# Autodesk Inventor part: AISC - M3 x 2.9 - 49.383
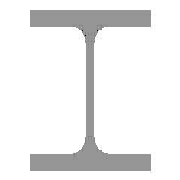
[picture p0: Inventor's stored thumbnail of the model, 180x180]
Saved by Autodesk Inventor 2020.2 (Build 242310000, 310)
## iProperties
_CCFamilyMember: 14
_CCFamilyDisplayName: ANSI M - M-Shape — Sizes in parentheses have been withdrawn
_FrameMemberDoc: Frame Member File
_Version: 15.0.0
_GetPNFromCC: 1
Created: 2020-01
Part Number: AISC - M3 x 2.9 - 49.383
Material: Steel, Mild
Description: M-Shape
Document SubType Name: Modeling
Standard: ANSI
Designer: thira
Standards Organization: ANSI
Language: en-US
Size Designation: M3 x 2.9
Categories: <MemberInstance><Categories><Category DisplayName="Structural Shapes" InternalName="089c4875-fa83-4c05-b084-43b9cc11f5ed" Mnemonic="GRDR"><CategoryParameter Dis
Stock Number: M3 x 2.9
Density: 7.85 g/cm^3
Appearance: Semi-Polished
G_L: 49.383 in
G_W: 2.250 in
G_H: 3.000 in
+2923C170-05DA-4238-8417-804BEE138335+CUTDETAIL1: Miter 45.00 deg
+5A0D731E-022E-4378-A517-99784A717457+CUTDETAIL2: Miter 45.00 deg
IsCustomPart: 1
Author: thira
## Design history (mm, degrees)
node "Start Plane"
node "End Plane"
sketch "Sketch"
  geometry: L1 (-28.575, -38.1)-(-28.575, -34.798); L2 (-28.575, -34.798)-(-10.541, -34.798); L3 (-1.143, -25.4)-(-1.143, 0); L4 (-1.143, 0)-(0, 0); L5 (0, 0)-(0, -38.1); L6 (0, -38.1)-(-28.575, -38.1); L7 (-60, 0)-(80, 0); L8 (0, -60)-(0, 80); L9 (28.575, -38.1)-(28.575, -34.798); L10 (28.575, -34.798)-(10.541, -34.798); L11 (0, -38.1)-(28.575, -38.1); L12 (1.143, -25.4)-(1.143, 0); L13 (1.143, 0)-(0, 0); L14 (-28.575, 38.1)-(-28.575, 34.798); L15 (0, 38.1)-(-28.575, 38.1); L16 (0, 38.1)-(28.575, 38.1); L17 (28.575, 34.798)-(10.541, 34.798); L18 (-28.575, 34.798)-(-10.541, 34.798); L19 (1.143, 25.4)-(1.143, 0); L20 (-1.143, 25.4)-(-1.143, 0); L21 (28.575, 38.1)-(28.575, 34.798); L22 (0, 108)-(0, -88) reference; L23 (-88, 0)-(108, 0) reference; A1 r 9.398 centre (-10.541, 25.4) between (-1.143, 25.4) and (-10.541, 34.798); A2 r 9.398 centre (10.541, 25.4) between (10.541, 34.798) and (1.143, 25.4); A3 r 9.398 centre (10.541, -25.4) between (1.143, -25.4) and (10.541, -34.798); A4 r 9.398 centre (-10.541, -25.4) between (-10.541, -34.798) and (-1.143, -25.4); 4 further points
  constraints: 42 end point, 11 symmetric about line, 8 point on circle, 8 point on line, 8 tangent, 4 centre point, 4 collinear, 4 parallel, 3 equal radius, 1 perpendicular, 1 vertical, 13 other
  dimensions: "d1" = 38.1 vertical distance of L1.start L3.end (= 0.5 x G_H); "d2" = 3.302 distance between parallel lines of L2 L6 (= G_T1); "d3" = 28.575 distance from line of L5.end L1 (= 0.5 x G_W); "d4" = 1.143 distance between parallel lines of L5 L3 (= 0.5 x G_T); "d13" = 9.398 radius of A1 (= G_IR)
extrude "Body" new body sketch "Sketch" stored distance "d5" = 1254.32157 (= G_L); taper "d6" = 0 deg
node "Driven Length"
  sketch "Sketch4"
    geometry: L1 (0, 0)-(10, 0) reference
    constraints: 2 end point, 1 horizontal
  workplane "Work Plane3"
  sketch "Sketch5"
    geometry: L1 (-2, -27.161)-(12, -27.161) reference; L2 (-2, 1227.161)-(12, 1227.161) reference
    dimensions: "d15" = 1254.32157 distance between parallel lines of L1 L2 (derived)
workplane "Work Plane4"
split "Split1"
workplane "Work Plane5"
split "Split2"
body "Solid1"
other parameters: "G_W" = 57.15 [user parameter; used in 1 equation term], "G_H" = 76.2 [user parameter; used in 1 equation term], "G_T" = 2.286 [user parameter; used in 1 equation term], "G_T1" = 3.302 [user parameter; used in 1 equation term], "G_IR" = 9.398 [user parameter; used in 1 equation term], "G_L" = 1254.32157 (= d15) [user parameter; used in 1 equation term], "G_OFFSET_START" = 27.16079 [user parameter; used in 1 equation term], "G_OFFSET_END" = 27.16079 [user parameter; used in 1 equation term], "d11" = -27.16079 (= -G_OFFSET_START), "d12" = 1227.16079 (= G_OFFSET_END + B_L), "B_L" = 1200 [user parameter; used in 1 equation term], "d14" = 90 deg
